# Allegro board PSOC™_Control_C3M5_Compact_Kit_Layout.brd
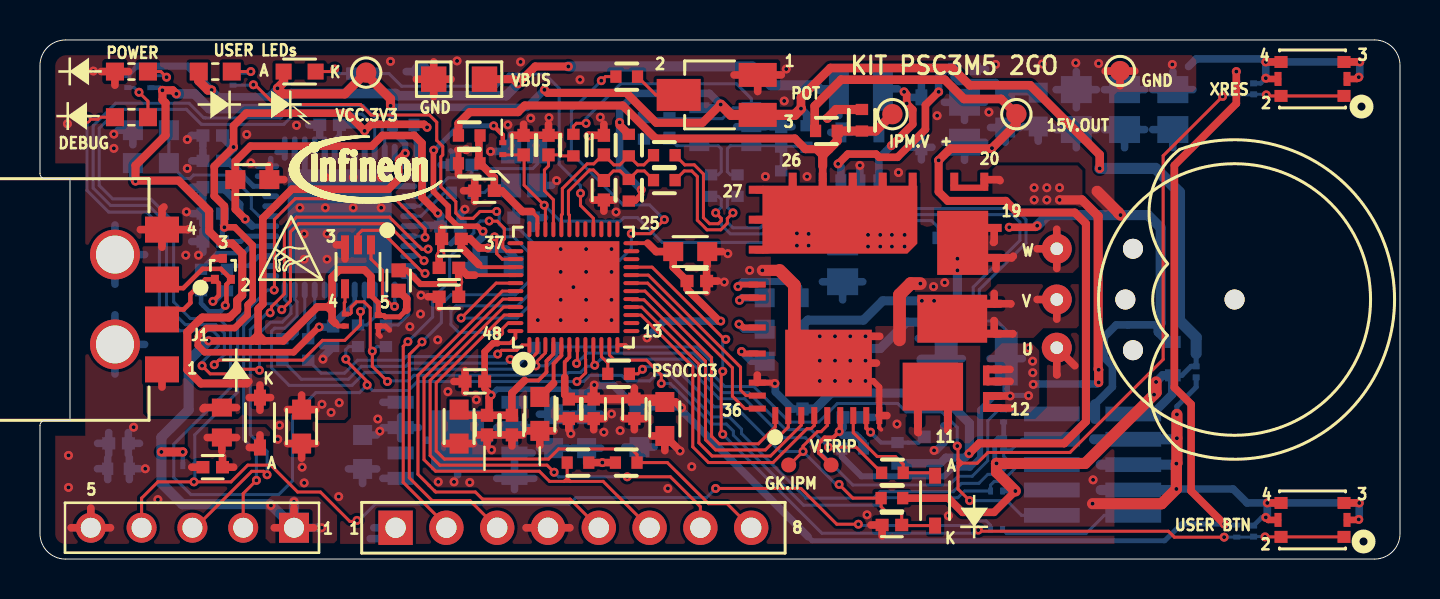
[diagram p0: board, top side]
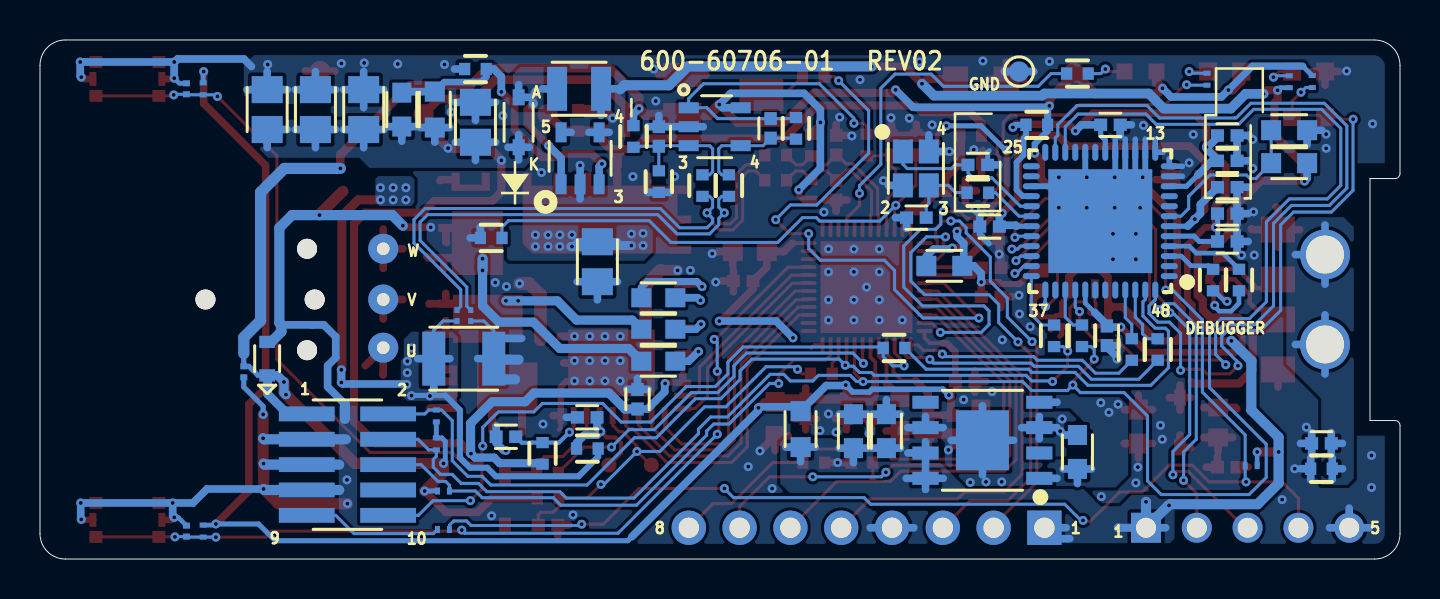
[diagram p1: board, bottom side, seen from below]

Outline 68 x 26 mm; copper layers: TOP, BOTTOM. Coordinates in mm from the lower left corner of the outline.
Outline path: 0,24.73 arc(0.37,25.62) 1.27,26 66.73,26 arc(67.63,25.63) 68,24.73 68,1.27 arc(67.63,0.37) 66.73,0 1.27,0 arc(0.37,0.37) 0,1.27 0,6.69 arc(0.07,6.87) 0.25,6.94 1.5,6.94 1.5,19.05 0.25,19.05 arc(0.07,19.13) 0,19.31 0,24.73

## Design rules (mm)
constraint set DEFAULT: min track width 0.152
net group DP1: nets N11111 N367460
net group DP2: nets IU IU0
net group IDC_LINK_PSEUDO: nets IDC_LINK_PSEUDO_N IDC_LINK_PSEUDO_P

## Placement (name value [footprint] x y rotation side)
C1  2.2nF  [CAPC1608_0603M]  49.91 22.51 90 bottom
C2  10uF  [CAPC2012_0805M]  46.23 21.87 90 bottom
C3  10uF  [CAPC2012_0805M]  51.82 22.51 90 bottom
C4  10uF  [CAPC2012_0805M]  54.23 22.51 90 bottom
C5  10uF  [CAPC2012_0805M]  56.64 22.51 90 bottom
C6  1uF  [CAPC1608_0603M]  16.13 5.36 90 bottom
C7  10uF  [CAPC1608_0603M]  13.08 6.63 270 top
C8  10uF  [CAPC1608_0603M]  25.68 6.41 90 bottom
C9  1uF  [CAPC1608_0603M]  27.33 6.41 90 bottom
C10  2.2uF  [CAPC1005_0402M]  8.64 4.6 180 top
C11  0.1uF  [CAPC1005_0402M]  3.93 5.79 0 bottom
C12  0.1uF  [CAPC1005_0402M]  14.48 21.75 180 bottom
C13  15pF  [CAPC1005_0402M]  21.11 19.74 180 bottom
C14  15pF  [CAPC1005_0402M]  24.18 17.1 0 bottom
C15  4.7uF  [CAPC1608_0603M]  10.62 19 0 top
C16  0.1uF  [CAPC1005_0402M]  8.64 18.62 180 bottom
C17  0.1uF  [CAPC1005_0402M]  20.52 16.65 0 bottom
C18  0.1uF  [CAPC1005_0402M]  14.66 11.18 270 bottom
C19  10uF  [CAPC1005_0402M]  8.64 21.21 180 bottom
C20  0.1uF  [CAPC1005_0402M]  8.64 19.94 180 bottom
C21  0.1uF  [CAPC1005_0402M]  8.64 17.3 180 bottom
C22  0.1uF  [CAPC1005_0402M]  8.64 15.9 180 bottom
C23  0.47nF  [CAPC1005_0402M]  38.13 8.01 90 bottom
C24  22uF  [CAPC2012_0805M]  40.13 14.89 270 bottom
C25  1uF  [CAPC1608_0603M]  37.08 13.09 180 bottom
C26  1uF  [CAPC1608_0603M]  37.08 11.51 0 bottom
C27  1uF  [CAPC1608_0603M]  37.08 9.91 0 bottom
C28  0.47nF  [CAPC1005_0402M]  44.7 6.13 0 bottom
C30  4700pF  [CAPC1005_0402M]  40.64 7.1 0 bottom
C31  10uF  [CAPC1005_0402M]  22.35 6.71 270 top
C32  0.1uF  [CAPC1005_0402M]  23.6 6.71 270 top
C33  10uF  [CAPC1005_0402M]  20.45 13.14 180 top
C34  0.1uF  [CAPC1005_0402M]  20.45 14.58 180 top
C35  10uF  [CAPC1608_0603M]  31.24 7.01 270 top
C36  0.1uF  [CAPC1005_0402M]  29.72 7.52 270 top
C37  10uF  [CAPC1608_0603M]  32.51 15.4 0 top
C38  0.1uF  [CAPC1005_0402M]  32.84 13.92 0 top
C39  10uF  [CAPC1608_0603M]  20.95 6.63 270 top
C40  0.1uF  [CAPC1005_0402M]  21.74 8.89 180 top
C41  1uF  [CAPC1005_0402M]  27.69 7.52 270 top
C42  0.1uF  [CAPC1005_0402M]  26.44 7.52 270 top
C43  4.7uF  [CAPC1608_0603M]  24.99 7.27 270 top
C44  0.22uF  [CAPC1005_0402M]  20.57 16.03 180 top
C45  1UF  [CAPC0603_0201N]  57.81 9.38 90 bottom
C46  100pF  [CAPC1005_0402M]  37.06 21.16 90 bottom
C47  100pF  [CAPC1005_0402M]  25.43 20.73 90 top
C48  0.1uF  [CAPC0603_0201N]  60.68 1.4 270 bottom
C49  0.1uF  [CAPC0603_0201N]  60.68 23.55 270 bottom
C50  100pF  [CAPC1005_0402M]  31.47 21.57 90 bottom
C51  0.1uF  [CAPC1005_0402M]  22.23 18.44 180 top
C52  0.1uF  [CAPC0603_0201N]  16.92 11.94 90 top
C53  10nF  [CAPC1005_0402M]  24.18 20.73 90 top
C56  1nF  [CAPC1005_0402M]  42.6 1.71 180 top
C57  100pF  [CAPC1005_0402M]  28.19 20.73 90 top
C58  100pF  [CAPC1005_0402M]  28.19 18.47 270 top
D1  SCHOTTKY DIODE  [SOD2512X110N]  11 6.84 270 top
D2  SCHOTTKY DIODE  [SOD2512X110N]  44.07 21.87 90 bottom
D3  150060VS75000  [LEDC1608_0603M]  4.57 24.41 90 top
D4  ESD5V3U2U-03F  [SOTFL40P120X59-3N]  9.14 14.53 90 top
D6  ESD5V0D5-TP  [SODFL1608X77M]  56.64 10.04 270 bottom
D7  RED  [LEDC1608X71N_WURTH]  12.98 24.41 180 top
D8  150060VS75000  [LEDC1608_0603M]  8.76 24.41 270 top
D9  150060VS75000  [LEDC1608_0603M]  4.57 22.13 90 top
D10  SCHOTTKY DIODE  [SOD2512X110N]  44.75 2.93 90 top
FB1  60 OHM  [INDC1608_0603N]  9.09 6.84 270 top
FB2  120 OHM  [INDC1005_0402M]  17.93 13.95 90 top
J1  629004113921  [WURTH_629004113921]  6.1 9.5 270 top
J2  HDR 5  [CTST254P1X05_W260]  12.7 1.57 180 top
J3  HDR 5x2  [SAMTEC_FTSH-105-01-L-DV-K-P-TR]  52.63 4.73 270 bottom
J4  CON 8  [RTST254P1X08_W265]  17.78 1.57 0 top
L1  10uH  [IND_74479887310A]  41.05 23.55 0 bottom
M1  BLDC Motor  [MOTOR_1103_KV2230]  59.73 13 0 top
NOREF  -  []  3.75 10.75 90 top
NOREF#2  -  []  35.88 22.25 90 top
NOREF#3  -  []  61.98 0.51 90 top
NOREF#4  -  []  45.11 8.69 90 top
NOREF#5  -  []  44.75 1.68 90 top
NOREF#6  -  []  47.98 12.25 0 top
NOREF#7  -  []  12.17 7.79 90 top
NOREF#8  -  []  0.45 25.69 0 top
NOREF#9  -  []  59.73 7.16 0 top
NOREF#10  -  []  44.79 20.92 90 top
NOREF#11  -  []  32.23 24.95 0 top
NOREF#12  -  []  35.88 22.25 90 top
NOREF#13  -  []  23.56 20.41 0 top
NOREF#14  -  []  17 13.96 90 top
NOREF#15  -  []  61.98 0.51 0 top
NOREF#16  -  []  66.73 0 90 top
NOREF#17  -  []  42.4 22.45 90 top
NOREF#18  -  []  12.18 24.41 0 top
NOREF#19  -  []  54.26 17.04 0 top
NOREF#20  -  []  0 24.73 0 top
NOREF#21  -  []  11 5.59 90 top
NOREF#22  -  []  61.98 22.59 0 top
NOREF#23  -  []  62.05 1.11 90 top
NOREF#24  -  []  23.16 18.26 90 top
NOREF#25  -  []  61.98 22.59 90 top
NOREF#26  -  []  78.49 26.09 0 top
NOREF#27  -  []  18.88 3.45 0 top
NOREF#28  -  []  18.03 5.31 90 top
NOREF#29  -  []  43.34 22.82 0 top
NOREF#30  -  []  22.88 3.45 90 top
NOREF#31  -  []  24.86 18.71 90 top
NOREF#32  -  []  44.03 1.98 90 top
NOREF#33  -  []  59.73 7.16 90 top
NOREF#34  -  []  44.07 20.62 90 top
NOREF#35  -  []  62.05 23.19 90 top
NOREF#36  -  []  23.16 18.26 0 top
NOREF#37  -  []  5.45 19.05 0 top
NOREF#38  -  []  39.7 22.45 0 top
NOREF#39  -  []  45.11 11.39 0 top
NOREF#40  -  []  7.12 -10.33 90 top
NOREF#41  -  []  6.1 9.5 90 top
NOREF#42  -  []  61.9 24.04 0 top
NOREF#43  -  []  62.05 23.19 0 top
NOREF#44  -  []  62.05 1.11 0 top
NOREF#45  -  []  6.1 12 90 top
NOREF#46  -  []  15.9 15.74 0 top
NOREF#47  -  []  45.31 10.04 0 top
NOREF#48  -  []  -337.11 -214.42 0 top
NOREF#49  -  []  18.03 7.85 0 top
NOREF#50  -  []  61.9 1.96 0 top
NOREF#51  -  []  10.27 9.24 0 top
NOREF#52  -  []  14.8 13.96 0 top
NOREF#53  -  []  -37.11 -29.41 0 top
NOREF#54  -  []  44.03 3.88 0 top
NOREF#55  -  []  74.73 66.61 0 top
NOREF#56  -  []  15.25 13.54 90 top
NOREF#57  -  []  39.95 23.55 0 top
NOREF#58  -  []  32.23 21.55 90 top
NOREF#59  -  []  48.21 149.92 0 top
R1  240K  [RESC1608_0603M]  48.26 22.51 90 bottom
R3  1M OHM  [RESC1005_0402M]  3.93 4.52 0 bottom
R4  22K  [RESC1005_0402M]  46.23 24.54 0 bottom
R5  0 OHM  [RESC1005_0402M]  18.16 21.75 0 bottom
R7  560 OHM  [RESC0603_0201N]  5.54 23.91 90 bottom
R8  4.7K  [RESC1608_0603M]  5.54 19.83 180 bottom
R9  0 OHM  [RESC1005_0402M]  12.12 10.49 90 bottom
R10  10K  [RESC1608_0603M]  5.54 21.48 180 bottom
R11  0 OHM  [RESC1005_0402M]  13.41 10.49 90 bottom
R12  510 OHM  [RESC1005_0402M]  21.11 18.34 180 bottom
R13  33 OHM  [RESC1005_0402M]  8.05 13.97 90 bottom
R14  33 OHM  [RESC1005_0402M]  9.35 13.97 90 bottom
R16  1 Ohm  [RESC3225X70N]  46.81 10.04 180 bottom
R18  680K  [RESC1005_0402M]  42.88 5.29 90 bottom
R19  1K  [RESC1005_0402M]  40.63 5.53 0 bottom
R20  10K  [POT_ST-32ETB]  33.93 23.25 90 top
R21  1K  [RESC1005_0402M]  29.34 24.16 0 top
R22  0 Ohm  [RESC1608_0603M]  29.97 6.51 90 bottom
R23  0 Ohm  [RESC1608_0603M]  22.78 14.69 0 bottom
R24  4.7K  [RESC1005_0402M]  26.9 4.83 180 top
R25  4.7K  [RESC1005_0402M]  29.31 4.83 0 top
R26  470 OHM  [RESC1005_0402M]  16.13 24.31 180 bottom
R29  560 OHM  [RESC0603_0201N]  9.65 24.03 90 bottom
R31  1K  [RESC1005_0402M]  34.88 18.7 90 bottom
R32  1K  [RESC1005_0402M]  26.67 20.73 270 top
R33  1K  [RESC1005_0402M]  33.56 18.7 90 bottom
R34  10K  [RESC0603_0201N]  59.84 1.4 270 bottom
R35  4.7K  [RESC0603_0201N]  59.84 23.55 270 bottom
R36  10K  [RESC1005_0402M]  30.2 21.57 90 bottom
R37  47K  [RESC1005_0402M]  21.46 21.21 0 top
R38  9.1K  [RESC1005_0402M]  21.46 19.82 180 top
R39  0 OHM  [RESC1005_0402M]  15.9 11.18 270 bottom
R40  0 OHM  [RESC1005_0402M]  17.3 11.18 270 bottom
R42  10K  [RESC0603_0201N]  47.83 3.41 180 bottom
R43  10K  [RESC0603_0201N]  48.18 5.77 270 bottom
R44  10K  [RESC0603_0201N]  48.18 7.17 90 bottom
R47  560 OHM  [RESC0603_0201N]  4.39 23.91 270 bottom
R48  0 OHM  [RESC1005_0402M]  28.93 9.28 0 top
R50  10K  [RESC0603_0201N]  7.44 4.68 180 bottom
R51  0 OHM  [RESC0603_0201N]  47.83 1.48 0 bottom
R52  4.7K  [RESC0603_0201N]  15.27 11.97 90 top
R53  0 OHM  [RESC1005_0402M]  25.3 10.57 180 bottom
R59  100K  [RESC0603_0201N]  23.14 20.55 270 top
R61  910 OHM  [RESC1005_0402M]  31.22 18.98 180 top
R62  4.7K  [RESC1005_0402M]  42.6 3.05 180 top
R63  4.7K  [RESC1005_0402M]  42.62 4.32 0 top
R64  10K  [RESC1005_0402M]  29.44 18.47 90 top
R66  910 OHM  [RESC1005_0402M]  31.22 20.22 180 top
R67  10K  [RESC1005_0402M]  29.44 20.73 270 top
R68  20K  [RESC1005_0402M]  38.33 21.16 270 bottom
R69  20K  [RESC1005_0402M]  37.06 18.9 270 bottom
R70  0 OHM  [RESC1005_0402M]  39.32 21.44 180 top
R71  0 OHM  [RESC1005_0402M]  41.1 21.98 90 top
SW1  435171014816  [SW_435171014816]  63.63 24.04 180 top
SW2  435171014816  [SW_435171014816]  63.63 1.96 180 top
TH1  100K  [RESC1005_0402M]  45.44 16.08 0 bottom
TIE1  Net Tie  [NET_TIE_COPPERTRACE]  47.15 12.2 90 bottom
TIE2  Net Tie  [NET_TIE_COPPERTRACE]  46.47 12.2 90 bottom
TP2  TP_SMD  [TP102C]  54 24.44 0 top
TP3  TP_SMD  [TP102C]  16.31 24.36 0 top
TP4  TP_SMD  [TP102C]  42.62 22.28 0 top
TP5  TP_SMD  [ICT_TP_SMD_030RD_NSP]  39.56 4.71 0 top
TP8  TP_SMD  [ICT_TP_SMD_030RD_NSP]  37.43 4.71 0 top
TP9  TP_SMD  [TP102C]  19.05 24.41 180 bottom
TP10  TP_SMD  [TP102C]  48.82 22.28 0 top
TP11  PCB SMD TP  [TP_SMD_SQ_127MM]  22.23 24.03 0 top
TP12  PCB SMD TP  [TP_SMD_SQ_127MM]  19.68 24.03 0 top
U1  PSC3M5FDS2LGQ1  [VQFN40P600X600X90-49N_NOFID]  26.67 13.62 90 top
U2  XMC4200-Q48F256 BA  [QFN50P700X700X90-49N_NOFID]  14.99 16.92 0 bottom
U3  IRSM836-044MA  [PQFN65P1200X1200X100-36N_INFINEON]  41.75 13.07 90 top
U4  TLS208D1EJV33XUMA1  [SOIC127P600X170-8_H265X300N]  20.88 5.95 0 bottom
U5  MIC2250-1YD5-TR  [SOT95P280X110-5N]  41 20.07 90 bottom
U6  AD8615AUJZ-REEL  [SOT95P280X110-5N]  34.27 21.65 180 bottom
U7  SN74LVC1G126DCKT  [SOT65P210X110-6N_TI]  15.9 14.64 270 top
Y1  12MHZ  [OSCCC200X250X60-4N_ECS]  24.21 19.56 270 bottom

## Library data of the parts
C1-C28 C30-C53 C56-C58 = CAP-NP
D1 D2 D10 = DIO-SCHOTTKY
D3 D7-D9 = DIO-LED
D4 = ESD5V3U2U-03F
D6 = DIO-TVS
FB1 FB2 = FB
J1 = USB-TYPE_A-2SH
J2 = PLG-5-J
J3 = PLG-10-ODD-EVEN-J
J4 = SKT-8-ALT-J
L1 = IND
M1 = BLDC_Motor_1103-KV2230
R1 R3-R5 R7-R14 R16 R18 R19 R21-R26 R29 R31-R40 R42-R44 R47 R48 R50-R53 R59 R61-R64 R66-R71 = RES
R20 = POT_1_2_3
SW1 SW2 = SWITCH-PB-12-34-G56
TH1 = THERMISTOR
TIE1 TIE2 = NET-TIE2: User Part Number: Part No
TP2-TP4 TP9 TP10 = TP_SMD
TP5 TP8 = TP_SMD: User Part Number: Part No
TP11 TP12 = TP
U1 = IC_PSC3M5FDS2LGQ1_VQFN-48
U2 = IC_XMC4200-Q48F256
U3 = IC_IRSM836-024MA
U4 = IC_TLS208D1EJV33_0
U5 = IC_MIC2250-1YD5
U6 = IC_AD8615AUJZ
U7 = IC_SN74LVC1G126DCK
Y1 = XTAL-4P-2G4G

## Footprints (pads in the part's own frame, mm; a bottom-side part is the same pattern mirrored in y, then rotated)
CAPC0603_0201N
  rect 0.3x0.35 smd: 1(-0.275,0) 2(0.275,0)
CAPC1005_0402M
  rect 0.65x0.62 smd: 1(-0.49,0) 2(0.49,0)
CAPC1608_0603M
  rect 1x0.95 smd: 1(-0.85,0) 2(0.85,0)
CAPC2012_0805M
  rect 1.35x1.55 smd: 1(-1,0) 2(1,0)
CTST254P1X05_W260
  rect 1.5x1.5 hole 1: 1(0,0)
  round 1.5 hole 1: 2(2.54,0) 3(5.08,0) 4(7.62,0) 5(10.16,0)
ICT_TP_SMD_030RD_NSP
  round 0.75 smd: 1(0,0)
IND_74479887310A
  rect 1x2.2 smd: 1(-1.1,0) 2(1.1,0)
INDC1005_0402M
  rect 0.7x0.72 smd: 1(-0.51,0) 2(0.51,0)
INDC1608_0603N
  rect 0.9x1 smd: 1(-0.75,0) 2(0.75,0)
LEDC1608_0603M
  rect 0.9x0.9 smd: A(0,-0.826) K(0,0.826)
LEDC1608X71N_WURTH
  rect 0.8x0.8 smd: A(0.8,0) K(-0.8,0)
MOTOR_1103_KV2230
  round 1 hole 1.4 unplated: (-5.461,0) (-5.08,2.54) (-5.08,-2.54)
  round 0 hole 1.422 unplated: (0,5.84) (0,-5.84) (5.84,0)
  round 1 hole 4 unplated: (0,0)
  round 1.5 hole 0.635: U(-8.89,-2.413) V(-8.89,0) W(-8.89,2.54)
NET_TIE_COPPERTRACE
  rect 0.3x0.25 smd: 1(-0.275,0) 2(0.275,0)
OSCCC200X250X60-4N_ECS
  rect 1.2x1 smd: 1(-0.85,-0.65) 2(0.85,-0.65) 3(0.85,0.65) 4(-0.85,0.65)
POT_ST-32ETB
  rect 1.2x1.9 smd: 1(1,-1.95) 3(-1,-1.95)
  rect 1.6x2.2 smd: 2(0,2)
PQFN65P1200X1200X100-36N_INFINEON
  rect 0.85x0.3 smd: 1(-5.887,4.982) 2(-5.887,4.332) 3(-5.887,3.682) 4(-5.887,3.033) 5(-5.887,2.383) 6(-5.887,1.733) 7(-5.887,1.083) 8(-5.887,0.433) 9(-5.887,-0.217)
  rect 0.78x0.4 smd: 10(-5.923,-2.148) 11(-5.923,-3.648)
  rect 0.4x0.75 smd: 12(-5.507,-5.963) 13(-4.908,-5.963) 14(-4.178,-5.963) 15(-3.578,-5.963) 16(-1.788,-5.963) 17(-0.288,-5.963) 18(2.012,-5.962) 19(3.512,-5.962) 27(5.422,5.932) 28(3.923,5.932) 29(2.422,5.932)
  rect 0.7x0.4 smd: 20(5.928,-5.468) 21(5.928,-3.968)
  rect 0.75x0.4 smd: 22(5.902,-1.887) 23(5.902,-0.388) 24(5.902,1.113) 25(5.902,2.612) 26(5.902,4.113)
  rect 0.3x0.85 smd: 30(0.673,5.882) 31(0.023,5.882) 32(-1.478,5.882) 33(-2.777,5.882) 34(-4.237,5.882) 35(-4.887,5.882) 36(-5.537,5.882)
  rect 3.34x4.33 smd: 39(-3.259,2.322)
QFN50P700X700X90-49N_NOFID
  oval 0.85x0.3 smd: 1(-3.45,2.75) 2(-3.45,2.25) 3(-3.45,1.75) 4(-3.45,1.25) 5(-3.45,0.75) 6(-3.45,0.25) 7(-3.45,-0.25) 8(-3.45,-0.75) 9(-3.45,-1.25) 10(-3.45,-1.75) 11(-3.45,-2.25) 12(-3.45,-2.75) 25(3.45,-2.75) 26(3.45,-2.25) 27(3.45,-1.75) 28(3.45,-1.25) 29(3.45,-0.75) 30(3.45,-0.25) 31(3.45,0.25) 32(3.45,0.75) 33(3.45,1.25) 34(3.45,1.75) 35(3.45,2.25) 36(3.45,2.75)
  oval 0.3x0.85 smd: 13(-2.75,-3.45) 14(-2.25,-3.45) 15(-1.75,-3.45) 16(-1.25,-3.45) 17(-0.75,-3.45) 18(-0.25,-3.45) 19(0.25,-3.45) 20(0.75,-3.45) 21(1.25,-3.45) 22(1.75,-3.45) 23(2.25,-3.45) 24(2.75,-3.45) 37(2.75,3.45) 38(2.25,3.45) 39(1.75,3.45) 40(1.25,3.45) 41(0.75,3.45) 42(0.25,3.45) 43(-0.25,3.45) 44(-0.75,3.45) 45(-1.25,3.45) 46(-1.75,3.45) 47(-2.25,3.45) 48(-2.75,3.45)
  rect 5.2x5.2 smd: H(0,0)
RESC0603_0201N
  rect 0.25x0.35 smd: 1(-0.3,0) 2(0.3,0)
RESC1005_0402M
  rect 0.56x0.62 smd: 1(-0.54,0) 2(0.54,0)
RESC1608_0603M
  rect 1x1 smd: 1(-0.9,0) 2(0.9,0)
RESC3225X70N
  rect 1.15x2.7 smd: 1(-1.5,0) 2(1.5,0)
RTST254P1X08_W265
  rect 1.72x1.72 hole 1.02: 1(0,0)
  round 1.72 hole 1.02: 2(2.54,0) 3(5.08,0) 4(7.62,0) 5(10.16,0) 6(12.7,0) 7(15.24,0) 8(17.78,0)
SAMTEC_FTSH-105-01-L-DV-K-P-TR
  rect 0.74x2.79 smd: 1(-2.54,-2.035) 2(-2.54,2.035) 3(-1.27,-2.035) 4(-1.27,2.035) 5(0,-2.035) 6(0,2.035) 7(1.27,-2.035) 8(1.27,2.035) 9(2.54,-2.035) 10(2.54,2.035)
SOD2512X110N
  rect 0.8x0.6 smd: A(1.25,0) K(-1.25,0)
SODFL1608X77M
  rect 0.61x0.787 smd: A(-0.838,0) K(0.838,0)
SOIC127P600X170-8_H265X300N
  rect 1.31x0.65 smd: 1(-2.845,1.905) 2(-2.845,0.635) 3(-2.845,-0.635) 4(-2.845,-1.905) 5(2.845,-1.905) 6(2.845,-0.635) 7(2.845,0.635) 8(2.845,1.905)
  rect 2.65x3 smd: H(0,0)
SOT65P210X110-6N_TI
  rect 0.95x0.4 smd: 1(-1.1,0.65) 2(-1.1,0) 3(-1.1,-0.65) 4(1.1,-0.65) 5(1.1,0.65)
SOT95P280X110-5N
  rect 1x0.55 smd: 1(-1.3,0.95) 2(-1.3,0) 3(-1.3,-0.95) 4(1.3,-0.95) 5(1.3,0.95)
SOTFL40P120X59-3N
  rect 0.45x0.4 smd: 1(-0.525,0.4) 2(-0.525,-0.4) 3(0.525,0)
SW_435171014816
  rect 0.65x0.6 smd: 1(-1.575,0.85) 2(1.575,0.85) 3(-1.575,-0.85) 4(1.575,-0.85)
  rect 0.35x0.7 smd: 5(-1.725,0) 6(1.725,0)
TP102C
  round 1.016 smd: 1(0,0)
TP_SMD_SQ_127MM
  rect 1.27x1.27 smd: 1(0,0)
VQFN40P600X600X90-49N_NOFID
  oval 0.8x0.2 smd: 1(-2.9,2.2) 2(-2.9,1.8) 3(-2.9,1.4) 4(-2.9,1) 5(-2.9,0.6) 6(-2.9,0.2) 7(-2.9,-0.2) 8(-2.9,-0.6) 9(-2.9,-1) 10(-2.9,-1.4) 11(-2.9,-1.8) 12(-2.9,-2.2) 25(2.9,-2.2) 26(2.9,-1.8) 27(2.9,-1.4) 28(2.9,-1) 29(2.9,-0.6) 30(2.9,-0.2) 31(2.9,0.2) 32(2.9,0.6) 33(2.9,1) 34(2.9,1.4) 35(2.9,1.8) 36(2.9,2.2)
  oval 0.2x0.8 smd: 13(-2.2,-2.9) 14(-1.8,-2.9) 15(-1.4,-2.9) 16(-1,-2.9) 17(-0.6,-2.9) 18(-0.2,-2.9) 19(0.2,-2.9) 20(0.6,-2.9) 21(1,-2.9) 22(1.4,-2.9) 23(1.8,-2.9) 24(2.2,-2.9) 37(2.2,2.9) 38(1.8,2.9) 39(1.4,2.9) 40(1,2.9) 41(0.6,2.9) 42(0.2,2.9) 43(-0.2,2.9) 44(-0.6,2.9) 45(-1,2.9) 46(-1.4,2.9) 47(-1.8,2.9) 48(-2.2,2.9)
  rect 4.6x4.6 smd: H(0,0)
WURTH_629004113921
  rect 1.3x1.7 smd: 1(0,0) 2(-2.5,0) 3(-4.5,0) 4(-7,0)
  round 2.5 hole 1.9: SH1(-1.25,-2.35) SH2(-5.75,-2.35)

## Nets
15V_OUT: C1.1 C2.1 C3.1 C4.1 C5.1 C23.1 D2.K R1.1 R18.1 R70.2 TP10.1(TP) U3.34
GND_EARTH: C11.1 J1.SH1 J1.SH2 R3.1
GND_SIGNAL: C2.2 C3.2 C4.2 C5.2 C6.2 C7.2 C8.2 C9.2 C10.2 C11.2 C12.2 C13.2 C14.2 C15.2 C16.2 C17.2 C18.2 C19.2 C20.2 C21.2 C22.2 C23.2 C24.2 C28.2 C30.2 C31.2 C32.2 C33.2 C34.2 C35.2 C36.2 C37.2 C38.2 C39.2 C40.2 C41.2 C42.2 C43.2 C44.2 C45.1 C46.2 C47.2 C48.1 C49.1 C51.2 C52.1 C53.2 C56.2 C57.2 C58.2 D3.K(CATHODE) D4.3 D6.A J1.4 J2.5 J3.3 J3.5 J3.7 J4.4 R3.2 R4.2 R10.2 R16.2 R20.1 R38.2 R69.2 SW1.3 SW1.4 SW1.5 SW1.6(GND#6) SW2.3 SW2.4 SW2.5 SW2.6(GND#6) TH1.2 TIE2.1 TP2.1(TP) TP9.1(TP) TP12.1(TP) U1.H U2.11 U2.12 U2.13 U2.14 U2.15 U2.16 U2.17 U2.20 U2.27 U2.H U3.9 U3.39 U4.3 U4.6 U4.H U5.2 U6.2(V-) U7.3 Y1.2 Y1.4(GND_2)
VBUS: C6.1 C7.1 D1.K L1.1 R7.1 R8.2 R71.2 TP11.1(TP) U4.1 U4.4 U5.4 U5.5(VIN)
VCC_3V3: C8.1 C9.1 C45.2 C52.2 D6.K(CATHODE) D7.A D8.A FB2.1 J2.1 J3.1 J4.1 R5.1 R20.3 R22.1 R24.1 R25.1 R42.1 R43.1 R44.1 R47.1 R50.2 R52.1 R62.1 R64.1 R67.1 R68.1 TP3.1(TP) U4.7 U4.8 U6.5 U7.5
VCCD: C43.1 U1.5
VDDA: C33.1 C34.1 FB2.2 R23.1 R59.1 U1.41
VDDC: C15.1 C16.1 C17.1 U2.6 U2.31
AN_B2: J4.2 U1.38
AN_B3: J4.3 U1.39
CS: U2.23 U2.40
DEBUG_LED: D9.K(CATHODE) U2.48
EN_IPM: R63.1 U1.7
GK_IPM: C56.1 D10.K R48.2 R62.2 TP8.1(TP) U3.5
IDC_LINK_OPAMP: C47.1 R32.2 U1.33
IDC_LINK_PSEUDO_N: C57.1 R66.2 R67.2 U1.32
IDC_LINK_PSEUDO_P: C58.1 R61.2 R64.2 U1.31
IPM_V+: C24.1 R37.1 R70.1 R71.1 TP4.1(TP) U3.22 U3.23 U3.24 U3.25 U3.26 U3.27 U3.28 U3.29
IU: R31.1 R61.1 TIE1.2(N2)
IU0: R33.1 R66.1 TIE2.2(N2)
M_SPEED_POT: R21.1 U1.42
OBD_PORST_L: J2.4 R50.1 R51.1 U2.32
OBD_TCK: J2.2 U2.34
OBD_TMS: J2.3 U2.33
OBD_UART_RX: R9.2 U2.46
OBD_UART_TX: R11.2 U2.45
OBD_USB_DM: D4.1 J1.2 R14.1
OBD_USB_DP: D4.2(IN2) J1.3 R13.1
OBD_VDDA: C12.1 C18.1 C19.1 C20.1 C21.1 C22.1 R5.2 U2.5 U2.10 U2.18 U2.28 U2.41
P8_0: J4.5 U1.43
P8_1: J4.6 R24.2 U1.44
P8_2: J4.7 U1.45
P8_3: J4.8 R25.2 U1.46
PSC3_UART_RX: R11.1 U1.1
PSC3_UART_TX: R9.1 U1.2
PWMUH: U1.20 U3.35
PWMUL: U1.17 U3.2
PWMVH: U1.19 U3.36
PWMVL: U1.16 U3.3
PWMWH: U1.18 U3.1
PWMWL: U1.15 U3.4
SWD_DIR: U2.37 U7.1
SWD_OUT: U2.35 U7.2
SWDCLK: J3.4 R39.2 R43.2 U1.8 U2.22
SWDIO: J3.2 R40.2 R44.2 R52.2 U1.9 U7.4(Y)
TDO: J3.6 R42.2 U1.11
TEMP: C53.1 R59.2 TH1.1 U1.34
U: M1.U U3.10 U3.11
USER_LED1: R26.1 U1.28
USER_LED2: R29.1 U1.47
USER_SW: C48.2 R34.2 SW2.1 SW2.2 U1.21
V: C26.2 M1.V U3.16 U3.17
V_TRIP: C30.1 R19.2 TP5.1(TP) U3.6
VB1: C25.2 U3.31
VB2: C26.1 U3.32
VB3: C27.1 U3.33
VBACKUP: C31.1 C32.1 C35.1 C36.1 C37.1 C38.1 C39.1 C40.1 C41.1 C42.1 R22.2 R34.1 R35.1 U1.4 U1.6 U1.12 U1.24 U1.48
VDC_LINK: C51.1 R37.2 R38.1 U1.35
VREF_EXT: C44.1 R23.2 U1.40
W: C27.2 M1.W U3.18 U3.19(W/VS3_2)
XRES_L_MCU: C49.2 J3.10 R35.2 R53.1 SW1.1 SW1.2 U1.3(XRES)
XTAL1: C13.1 U2.29 Y1.1
XTAL2: C14.1 R12.1 Y1.3
N07345: FB1.1 J1.1(VBUS)
N07349: C10.1 D1.A FB1.2
N08163: D2.A L1.2 U5.1
N11111: R14.2 U2.3
N20632: C1.2 R1.2 R4.1 U5.3
N32254: R12.2 U2.30
N37178: C28.1 R18.2 U3.8
N38243: C25.1 U3.30
N38502: R16.1 R19.1 TIE1.1 U3.12 U3.13 U3.14 U3.15 U3.20 U3.21
N50220: R8.1 R10.1 U2.7
N86492: D3.A R7.2
N117783: C46.1 R31.2 R68.2 R69.1 U6.3
N117862: C50.1 R33.2 R36.1 U6.4
N117920: C50.2 R32.1 R36.2 U6.1
N133373: D7.K(CATHODE) R26.2
N133421: D8.K(CATHODE) R29.2
N143868: R20.2(WIPER) R21.2
N214953: R39.1 U2.39
N215126: R40.1 U2.36
N223602: J3.9 R51.2
N254765: R53.2 U2.47
N255191: D9.A R47.2
N338896: D10.A R63.2 U3.7
N367460: R13.2 U2.4
N371560: R48.1 U1.10

Pads without a net: J3 8; U1 13 14 22 23 25 26 27 29 30 36 37; U2 1 2 8 9 19 21 24 25 26 38 42 43 44; U4 2 5

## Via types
v1: diameter 0.45, hole 0.2, TOP to BOTTOM, 298 vias

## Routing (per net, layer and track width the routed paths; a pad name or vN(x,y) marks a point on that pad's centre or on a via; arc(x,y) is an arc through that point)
15V_OUT: length 79.2
  TOP w0.305: U3.34 36.75,8.84 v1(36.75,8.79)
  TOP w0.381: U3.34 35.86,9.22
  TOP w0.406: 47.57,20.58 v1(47.6,20.58) ; v1(46.45,5.28) 46.96,5.8 51.21,5.8 52.3,6.89 52.3,16.79 51.74,17.35 48.87,17.35 48.29,17.94 45.39,17.94 44.93,18.39 v1(44.93,19.97)
  TOP w0.432: v1(47.6,20.58) 48.82,21.8 TP10.1 48.06,23.04 46.2,23.04 45.24,24.01 40.06,24.01 38.73,22.69 38.73,21.49 R70.2 ; v1(44.93,19.97) 45.52,20.55 47.55,20.55 47.57,20.58
  BOTTOM w0.381: 54.23,20.6 C4.1 ; C4.1 53.22,21.51 ; C4.1 55.24,21.51 ; C3.1 52.82,21.51 ; C3.1 51.82,20.6 ; C3.1 50.81,21.51 ; D2.K 44.07,21.26 ; D2.K 44.07,19.99 ; D2.K 43.54,20.62 ; D2.K 44.6,20.62 ; 46.23,19.97 C2.1 ; C2.1 45.22,20.87 ; C2.1 47.23,20.87 ; 47.53,21.61 R1.1 ; R1.1 48.26,20.88 ; R1.1 48.99,21.61 ; C23.1 37.62,7.52 36.77,8.37 36.77,8.77 v1(36.75,8.79) ; 56.64,20.6 C5.1 55.64,21.51 ; 49.91,20.93 C1.1 ; C1.1 50.62,21.66 ; C1.1 49.2,21.66
  BOTTOM w0.406: v1(46.45,5.28) 46.25,5.08 45.29,5.08 45.02,4.8 42.92,4.8 R18.1
  BOTTOM w0.457: v1(46.45,5.28) 46.47,5.3 46.47,6.8 45.39,7.88 43.74,7.88 43.3,8.31 39.55,8.31 38.75,7.52 C23.1
GND_EARTH: length 12.1
  BOTTOM w0.381: J1.SH2 3.75,16.73 ; J1.SH2 3.75,13.77 ; J1.SH2 5.23,15.25 ; 2.88,4.52 R3.1 ; R3.1 3.39,5.07 ; R3.1 3.39,3.98 ; 2.88,5.79 C11.1 ; C11.1 3.44,5.25 ; C11.1 3.44,6.34 ; J1.SH1 5.23,10.75 ; J1.SH1 3.75,12.23 ; J1.SH1 3.75,9.27
GND_SIGNAL: length 246.2
  TOP w0.203: U3.9 41.96,6.58 42.06,6.48
  TOP w0.254: 17.02,11.16 16.92,11.26 C52.1 17.27,11.67 17.48,11.46
  TOP w0.305: 20.85,20.5 20.92,20.43 R38.2 ; U3.9 41.96,8.62 41.66,8.92 v1(41.27,8.92)
  TOP w0.33: v1(61.29,24.08) 61.33,24.04 SW1.6 ; SW2.5 65.91,1.96 v1(65.94,1.99) ; v1(65.94,24.13) 65.85,24.04 SW1.5 ; SW2.6 61.42,1.96 v1(61.29,2.09)
  TOP w0.381: J1.4 6.1,17.53 6.2,17.63 ; J1.4 6.1,15.62 ; J1.4 5.02,16.5 ; J1.4 7.4,16.5 7.44,16.54 ; 3.06,24.41 D3.K ; D3.K 4.43,24.41 ; D3.K 3.75,23.73 ; C35.2 30.59,6.17 ; C35.2 31.25,6.17 v1(32,5.41) ; C35.2 31.24,5.43 ; 26.49,1.57 J4.4 24.31,1.57 ; 21.74,17.9 C51.2 ; C51.2 21.74,18.99 ; C51.2 21.18,18.44 ; 41.99,11.16 v1(41.27,11.16) ; 7.59,4.6 C10.2 ; C38.2 33.33,14.47 ; C38.2 33.89,13.92 ; C38.2 33.33,13.38 ; C43.2 25.7,6.42 ; C43.2 24.29,6.42 ; C43.2 24.99,5.69 ; 11.47,19.71 C15.2 12.2,19 ; 24.88,21.22 C47.2 ; C47.2 25.43,21.78 ; C47.2 25.97,21.22 ; TP12.1 19.68,24.9 ; TP12.1 18.82,24.03 ; TP12.1 19.68,23.17 ; TP12.1 20.55,24.03 ; 41.55,1.71 C56.2 42.11,1.16 ; 1.56,1.57 J2.5 ; J2.5 3.52,1.57 ; J2.5 2.54,2.55 ; 12.37,5.78 C7.2 ; C7.2 13.08,5.05 ; C7.2 13.79,5.78 ; 28.19,21.78 C57.2 27.44,21.22 v1(27.41,21.19) ; C40.2 21.25,9.44 ; C40.2 20.7,8.89 ; C40.2 21.25,8.35 ; U3.9 42.35,7.19 ; 21.81,6.22 C31.2 ; C31.2 22.35,5.66 ; C31.2 C32.2 ; C58.2 28.74,17.98 ; C58.2 28.19,17.42 ; C58.2 27.65,17.98 ; 8.71,15.06 D4.3 ; 27.69,6.48 C41.2 ; C41.2 28.23,7.03 ; C41.2 C42.2 ; SW2.3 v1(65.96,2.81) ; 25.9,7.03 C42.2 ; C42.2 26.44,6.48 ; 23.6,5.66 C32.2 ; C32.2 24.14,6.22 ; SW1.3 v1(65.99,24.89) ; U3.39 41.82,9.81 ; 29.18,7.03 C36.2 ; C36.2 29.72,6.48 ; C36.2 30.26,7.03 ; v1(61.37,2.81) SW2.4 ; v1(49.86,16.7) 49.78,16.62 v1(48.46,16.62) ; C34.2 19.96,15.19 v1(20.04,15.27) 20.04,15.87 20.04,15.99 C44.2 20.08,16.57 ; 54,23.7 TP2.1 ; TP2.1 54.74,24.44 ; TP2.1 53.26,24.44 ; 19.96,12.59 C33.2 19.4,13.14 ; 15.25,15.03 U7.3 14.82,15.74 ; 23.64,21.22 C53.2 ; C53.2 24.72,21.22 ; C53.2 24.18,21.78 ; 34.7,24.25 R20.1 ; R20.1 35.88,23.41 ; R20.1 37.07,24.25 ; 33.36,14.69 C37.2 34.09,15.4 ; 20.25,5.78 C39.2 21.66,5.78 ; SW1.4 v1(61.29,24.89) ; 20.92,19.27 R38.2
  TOP w0.559: v1(54.03,17.23) 53.92,17.33 53.92,17.35 52.86,18.42 ; v1(56.85,7.24) v1(56.85,6.05) 56.85,4.81 v1(56.82,4.78) v1(56.82,3.51) 56.08,2.77 v1(52.63,2.77) ; v1(36.12,14.46) 36.98,14.46
  TOP w0.635: 36.98,14.46 37.72,13.72 37.72,11.27 39.17,9.81 U3.39 ; 42.98,10.98 42.98,13.24 43.54,13.8 v1(44.02,13.8)
  BOTTOM w0.152: v1(21.25,17.52) 21.25,17.52 21.14,17.41 ; 45.31,10.78 45.31,11.43 45.8,11.92 TIE2.1
  BOTTOM w0.229: C48.1 61.09,2.09 v1(61.29,2.09) ; C49.1 61.03,23.83 v1(61.29,24.08)
  BOTTOM w0.254: 20.54,20.45 20.62,20.37 C13.2 ; C45.1 57.81,8.62 56.85,7.65 v1(56.85,7.24)
  BOTTOM w0.279: U2.14 12.74,21.03 ; U2.15 13.24,21.03 ; 12.24,21.03 U2.13 11.85,20.37 ; U2.16 13.74,21.03 ; 10.88,19.17 U2.11 ; U2.17 14.24,21.03 ; 11.54,20.05 U2.12 10.88,19.67
  BOTTOM w0.292: v1(14.27,19.12) 14.24,19.15 U2.17 ; v1(17.06,19.12) 17.06,18.96 17.35,18.67 U2.27 ; U2.14 12.74,19.25 v1(12.87,19.12) 12.94,19.12 13.24,19.41 U2.15 ; v1(14.27,17.59) 13.74,18.12 U2.16 ; U2.20 15.74,19.19 v1(15.66,19.12) ; C17.2 21.01,16.27 20.55,15.8
  BOTTOM w0.305: v1(26.54,6.28) 26.54,6.84 26.52,6.86
  BOTTOM w0.381: 45.19,6.67 C28.2 45.19,5.82 44.81,5.44 v1(44.7,5.44) ; 14.11,10.69 C18.2 14.66,10.62 14.15,10.11 v1(14.15,10.01) ; C24.2 41.14,13.89 ; C24.2 40.13,12.98 ; C24.2 39.13,13.89 ; 43.92,11.05 45.03,11.05 45.31,10.78 R16.2 ; v1(21.25,17.52) 21.14,17.41 21.14,17.41 21.01,17.28 C17.2 ; 7.59,18.62 C16.2 8.15,18.08 ; 1.56,1.57 J2.5 ; J2.5 2.54,2.55 ; J2.5 3.52,1.57 ; 45.22,22.87 C2.2 ; C2.2 46.23,21.97 ; C2.2 47.23,22.87 ; 26.62,7.26 C9.2 28.04,7.26 ; v1(61.37,2.81) 60.35,2.81 59.65,3.51 v1(56.82,3.51) ; v1(61.37,2.81) v1(65.96,2.81) 65.96,2.01 v1(65.94,1.99) ; v1(61.37,2.81) 61.37,2.16 v1(61.29,2.09) ; 26.49,1.57 J4.4 24.31,1.57 ; C4.2 54.23,24.42 ; C4.2 55.24,23.51 ; C4.2 53.22,23.51 ; C5.2 56.64,24.42 ; C5.2 57.65,23.51 ; C5.2 55.64,23.51 ; 17.15,6.58 U4.3 ; U4.3 18.03,6.03 ; U4.3 18.03,7.14 ; U4.3 18.92,6.58 ; 8.15,20.49 C20.2 7.59,19.94 ; 19.79,24.41 TP9.1 18.31,24.41 ; C30.2 41.69,7.1 ; R3.2 4.47,5.07 ; R3.2 4.98,4.52 ; R3.2 4.47,3.98 ; v1(7.37,21.01) 7.57,21.21 C19.2 8.15,20.67 ; v1(61.29,24.89) 61.27,24.89 61.12,25.04 57.81,25.04 57.43,24.67 ; v1(61.29,24.89) v1(61.29,24.08) ; v1(61.29,24.89) v1(65.99,24.89) 65.99,24.19 v1(65.94,24.13) ; C6.2 16.84,6.21 ; C11.2 4.42,6.34 ; C11.2 4.42,5.25 ; C11.2 4.97,5.79 ; v1(22.53,20.41) Y1.4 23.56,21.24 ; 51.82,22.6 C3.2 ; C3.2 51.82,24.42 ; C3.2 52.82,23.51 ; C3.2 50.81,23.51 ; C8.2 26.39,7.26 ; C8.2 25.68,7.99 ; C8.2 24.97,7.26 ; 13.99,21.21 C12.2 13.43,21.75 ; C46.2 37.06,22.21 ; C46.2 36.52,21.65 ; C46.2 37.6,21.65 ; 22.84,6.58 U4.6 ; U4.6 23.72,7.14 ; U4.6 24.61,6.58 ; 8.15,16.76 C21.2 ; C21.2 8.15,17.84 ; C21.2 7.59,17.3 ; C22.2 8.15,16.45 ; C22.2 7.59,15.9 ; C22.2 8.15,15.36 ; 52.75,7.76 53.62,8.62 53.62,9.68 53.21,10.09 53.21,11.13 53.81,11.73 54.39,11.73 54.41,11.73 55.93,11.73 55.93,11.73 ; 37.58,8.5 C23.2 ; C23.2 38.67,8.5 ; C23.2 38.13,9.05 ; 4.64,20.75 R10.2 3.91,21.48 ; 20.06,19.74 C13.2 ; 25.23,17.1 C14.2 24.67,16.56 ; 34.84,21.65 U6.2 36.3,21.65 ; 19.32,5.95 U4.H ; U4.H 22.44,5.95 ; U4.H 20.88,7.68 ; U4.H 20.88,4.22 ; R16.2 46.12,10.04 ; R16.2 44.51,10.04 ; R16.2 45.31,9.99 ; 41,19.5 U5.2 41,18.04 ; 46.49,16.08 TH1.2 45.98,16.62 ; 37.6,18.36 R69.2 36.52,18.36 ; Y1.2 25.59,18.71 ; R4.2 47.28,24.54
  BOTTOM w0.508: 53.04,3.46 J3.7 56.77,3.46 v1(56.82,3.51) ; v1(56.85,6.05) 56.79,6 J3.3 52.7,6 ; 53.04,4.73 J3.5 56.77,4.73 v1(56.82,4.78) ; D6.A 56.44,10.88 55.93,11.38 55.93,11.73 56.03,11.83 56.03,16.59 55.4,17.23 v1(54.03,17.23) 50.39,17.23 v1(49.86,16.7) ; 52.75,7.02 52.75,7.76 ; 44.07,9.99 45.31,9.99 45.31,9.5 44.81,9 44.25,9
  vias: v1(1.37,21.8) v1(1.42,5.19) v1(1.42,3.59) v1(2.67,24.44) v1(3.69,21.28) v1(3.69,20.57) v1(4.68,6.6) v1(5.26,4.52) v1(5.89,2.98) v1(7.32,17.39) v1(7.29,15.22) v1(7.37,19.56) v1(7.92,15.22) v1(10.34,21.26) v1(10.54,19.84) v1(11.89,6) v1(11.98,6.7) v1(12.83,21.72) v1(13,17.59) v1(13.11,4.6) v1(13.21,16.29) v1(13.21,15.02) v1(13.21,3.81) v1(14.35,16.29) v1(14.35,15.02) v1(14.94,3.13) v1(15.66,17.59) v1(16.89,7.01) v1(16.99,6.41) v1(17.06,17.59) v1(17.53,24.92) v1(18.49,11.64) v1(19.02,12.27) v1(19.05,13.21) v1(19.89,10.98) v1(19.91,3.87) v1(20.4,8.39) v1(20.7,3.87) v1(20.85,24.95) v1(21.31,20.5) v1(21.49,3.84) v1(21.82,7.98) v1(22.58,5.47) v1(23.39,21.75) v1(24.03,24.9) v1(24.54,22.08) v1(24.89,11.97) v1(25.45,22.1) v1(25.83,18.95) v1(26.04,15.52) v1(26.04,14.38) v1(26.04,12.98) v1(26.04,11.97) v1(26.67,13.62) v1(27,24.01) v1(27.3,15.52) v1(27.3,14.38) v1(27.3,12.98) v1(27.3,11.97) v1(28.02,22.13) v1(28.19,6.35) v1(28.57,15.52) v1(28.57,14.38) v1(28.57,12.98) v1(28.57,11.97) v1(28.57,7.27) v1(28.8,17.38) v1(29.01,6.43) v1(31.39,3.54) v1(32.59,4.63) v1(34.21,13.87) v1(34.39,15.3) v1(35.48,14.46) v1(36.27,19.16) v1(37.21,22.94) v1(37.31,24.54) v1(38.35,19.16) v1(38.99,11.16) v1(38.99,9.94) v1(38.99,8.92) v1(39.75,11.16) v1(39.75,9.94) v1(39.75,8.92) v1(40.51,11.16) v1(40.51,9.94) v1(40.51,8.92) v1(41,19.71) v1(41.27,9.94) v1(41.35,2.21) v1(42.85,6.76) v1(42.93,19.36) v1(44.68,13.64) v1(44.86,22.2) v1(45.24,13.85) v1(45.42,2.17) v1(47.45,22.38) v1(47.78,24.77) v1(50.11,24.79) v1(51.79,24.85) v1(52.65,3.97) v1(52.93,24.82) v1(56.62,24.77)
VBUS: length 75.8
  TOP w0.381: C7.1 13.08,8.22 ; C7.1 13.79,7.48 ; C7.1 12.37,7.48 ; 11,7.46 D1.K ; D1.K 11.53,8.09 ; D1.K 10.47,8.09 ; D1.K 11,8.72 ; 10.45,8.89 10.34,8.79
  TOP w0.406: v1(6.82,23.3) 6.64,23.48 v1(6.12,23.48) 6.12,23 6.28,22.84 6.28,21.22 4.78,19.71 v1(4.78,18.93) 4.8,18.95 6.93,18.95 8.46,17.43 8.46,16.41 9.07,15.8 9.61,15.8 10.11,15.3 10.11,13.21 9.86,12.96 9.86,12.51 9.84,12.49 9.84,12.46 9.5,12.12 9.48,12.12 9.45,12.09 8.12,12.09 8.01,11.99 7.99,11.99 7.37,11.36 7.37,9.48 8.05,8.79 10.34,8.79 ; v1(26.42,24.67) 24.77,24.67 v1(23.9,23.8) 23.67,24.03 TP11.1
  TOP w0.457: v1(39.37,22.08) 39.81,22.52 R71.2
  BOTTOM w0.229: v1(6.12,23.48) 5.99,23.61 R7.1
  BOTTOM w0.381: 17.15,4.04 U4.1 ; R8.2 4.64,19.06 v1(4.78,18.93) ; 39.95,22.22 L1.1 39.21,23.55 ; 41.44,21.37 U5.5 ; 40.55,21.37 U5.4 39.54,21.37 ; 15.42,4.51 C6.1 ; C6.1 16.13,3.78 ; C6.1 16.84,4.51 ; 17.15,7.85 U4.4
  BOTTOM w0.483: v1(6.82,23.3) 7.72,23.3 8.46,22.56 11.81,22.56 12.57,23.31 17.78,23.31 17.89,23.21 23.3,23.21 v1(23.9,23.8)
  BOTTOM w0.508: 38.99,23.52 38.79,23.73 36.55,23.73 35.61,24.67 v1(26.42,24.67)
  vias: v1(14.1,7.75) v1(14.55,7.35) v1(14.96,7.83)
VCC_3V3: length 188.7
  TOP w0.241: R52.1 15.2,11.67 15.2,11.67 14.9,11.67 14.77,11.8
  TOP w0.254: 18.3,12.45 17.97,12.13 17.26,12.13 17.19,12.19 16.94,12.19 C52.2 16.92,12.83 16.55,13.2 U7.5
  TOP w0.305: v1(30.06,18.5) 30.06,18.24 29.76,17.93 R64.1
  TOP w0.381: 14.4,12.63 14.4,12.6 14.61,12.4 ; 14.4,12.63 13.87,12.63 12.17,10.93 11.22,10.93 ; 14.4,12.63 14.61,12.83 ; 10.85,10.93 11.22,10.93 ; 10.85,10.93 10.84,10.92 10.59,10.92 ; 10.85,10.93 10.91,10.99 10.91,11.24 ; 11.22,10.93 10.91,11.24 ; FB2.1 18.34,13.03 18.34,12.49 18.3,12.45 ; 14.77,11.8 14.61,11.97 14.61,12.4 ; 14.61,12.83 14.61,12.4 ; 14.61,12.83 14.61,14.13 14.96,14.48 16.22,14.48 16.55,14.15 U7.5 ; R24.1 v1(28.12,4.83) R25.1 ; R62.1 45.42,3.05 46.13,2.34 47.7,2.34 v1(48.77,3.41) ; 10.91,11.24 10.59,10.92 ; 10.91,11.24 10.91,12.53 10.94,12.56 10.94,12.57 11.14,12.77 11.14,17.07 12.59,18.52 17.42,18.52 17.93,19.03 17.93,19.99 v1(18.26,20.32) ; 10.59,10.92 8.45,10.92 8.44,10.93 v1(8.43,10.93) ; 11.72,1.57 J2.1 ; J2.1 12.7,2.55 ; J2.1 13.68,1.57
  TOP w0.406: R67.1 28.98,21.73 v1(28.98,21.87) ; v1(25.22,23.5) 25.37,23.35 29.31,23.35 30.81,21.85 33.12,21.85 v1(34.04,22.76)
  TOP w0.432: v1(52.98,19.56) 52.98,20.25 49.5,23.73 46.48,23.73 45.62,24.59 39.52,24.59 38.05,23.12 v1(38.05,22.56)
  TOP w0.457: v1(17.53,22.7) 17.53,23.04 16.31,24.26 TP3.1 15.24,23.3 12.15,23.3 v1(11.87,23.58) 12.18,23.88 D7.A ; v1(8.58,23.49) 8.39,23.49 7.94,23.95 D8.A ; v1(7.14,5.36) v1(6.07,5.36)
  TOP w0.508: v1(34.04,22.76) 34.55,22.25 R20.3 37.74,22.25 v1(38.05,22.56)
  TOP w0.559: v1(55.8,8.87) 55.8,8.34 v1(55.7,8.23) 52.26,4.79 47.83,4.79 v1(47.83,4.79) 47.83,4.35 v1(48.77,3.41)
  BOTTOM w0.229: R50.2 v1(7.14,5.36)
  BOTTOM w0.241: 4.86,24.69 R47.1 ; v1(47.83,4.79) 47.83,4.8 47.74,4.89 47.74,5.89 47.91,6.07 48.18,6.07 R43.1 R44.1 ; v1(48.77,3.41) R42.1
  BOTTOM w0.254: D6.K 57.1,9.2 57.55,9.65 C45.2 57.81,10.29
  BOTTOM w0.305: v1(18.26,20.32) 18.26,20.79 17.62,21.43 17.62,21.62
  BOTTOM w0.356: v1(8.58,23.49) 7.38,24.69 4.86,24.69 ; 17.62,21.62 R5.1 17.62,22.64 17.57,22.7
  BOTTOM w0.381: 29.24,5.61 R22.1 ; R22.1 29.97,4.88 ; R22.1 30.7,5.61 ; v1(8.58,23.49) 8.93,23.14 11.44,23.14 v1(11.87,23.58) ; 22.84,4.04 U4.8 ; U4.8 23.72,4.6 ; U4.8 24.69,4.04 ; U4.8 23.72,3.49 ; v1(30.06,18.5) 28.98,19.58 v1(28.98,21.87) 28.98,22.51 29.79,23.32 33.48,23.32 v1(34.04,22.76) 33.87,22.6 U6.5 ; 16.69,1.57 J4.1 17.23,1.02 16.51,1.02 ; v1(17.53,22.7) 17.58,22.7 17.65,22.62 24.35,22.62 v1(25.22,23.5) ; 24.97,5.56 C8.1 26.39,5.56 ; 27.33,4.82 C9.1 ; C9.1 28.04,5.56 ; C9.1 26.62,5.56 ; v1(38.05,22.56) 38.33,22.28 R68.1 ; U4.7 24.61,5.31 ; U4.7 23.72,5.87 ; U4.7 23.72,4.76 ; 11.72,1.57 J2.1
  BOTTOM w0.406: v1(14.08,1.57) J2.1
  BOTTOM w0.432: v1(55.8,8.87) 56.13,9.2 D6.K 56.62,9.17 56.62,8.26 55.63,7.27 J3.1
  BOTTOM w0.457: v1(55.7,8.23) 55.8,8.34 v1(55.8,8.87)
  BOTTOM w0.508: v1(12.7,2.87) J2.1 11.58,2.68 v1(11.55,2.68) 11.48,2.75 7.12,2.75 6.07,3.8 v1(6.07,5.36) 6.07,6.1 7.43,7.46 7.43,9.93 v1(8.43,10.93)
  BOTTOM w0.559: v1(52.98,19.56) 55.78,19.56 56.97,18.37 56.97,11.94 57.81,11.1 57.81,10.29
VCCD: length 3
  TOP w0.191: U1.5 26.07,10.19 26.01,10.13 26.01,10.13 25.77,9.89 25.77,9.88 25.68,9.79 25.68,8.8
  TOP w0.381: 25.68,8.8 C43.1
VDDA: length 21.4
  TOP w0.191: U1.41 21.74,14.22
  TOP w0.229: R59.1 23.14,21.24 v1(22.68,21.7)
  TOP w0.279: v1(19.68,20.48) 19.68,20.43 19.67,20.42 19.67,18.41 20.41,17.67 20.41,17.13 20.88,16.67 21.87,16.67 22.12,16.41 v1(22.15,16.41)
  TOP w0.305: FB2.2 18.34,14.46 19.02,13.77 19.94,13.77 20.04,13.87 v1(20.94,13.87)
  TOP w0.381: 21.74,14.22 21.36,14.22 20.99,14.58 C34.1 v1(20.94,13.87) C33.1
  BOTTOM w0.254: v1(22.68,21.7) 20.95,21.7 19.73,20.48 v1(19.68,20.48)
  BOTTOM w0.381: v1(22.15,16.41) 22.15,16.15 21.82,15.81 21.82,14.75 R23.1 21.32,14.69 20.94,14.3 v1(20.94,13.87)
VDDC: length 22.8
  TOP w0.381: v1(19.89,17.32) 19.1,18.11 19.1,20.83 18.72,21.21 17.12,21.21 16.59,20.68 10.53,20.68 9.77,19.92 C15.1 9.77,17.52 v1(10.26,17.02)
  BOTTOM w0.254: U2.6 10.61,16.67 ; U2.31 19.17,16.67
  BOTTOM w0.381: 10.61,16.67 v1(10.26,17.02) 9.98,17.3 9.98,17.76 9.13,18.62 C16.1 ; v1(19.89,17.32) 20.03,17.18 C17.1 19.97,16.72 19.22,16.72 19.17,16.67
AN_B2: length 20.9
  TOP w0.152: J4.2 20.32,1.68 18.16,3.84 18.16,10.65 v1(18.39,10.89) ; v1(22.46,16.93) 22.47,16.92 22.86,16.92 23.22,16.57 23.22,16.03 23.14,15.96 23.14,15.6 23.32,15.42 U1.38
  BOTTOM w0.152: v1(22.46,16.93) 22.02,16.93 21.7,16.6 21.7,16.34 20.48,15.13 20.48,13.91 19.63,13.06 19.63,12.13 v1(18.39,10.89)
AN_B3: length 25.1
  TOP w0.152: v1(19.1,10.88) 18.47,10.24 18.47,4.07 19.61,2.93 21.5,2.93 J4.3 ; U1.39 23.11,15.02 22.84,15.29 22.84,16.03 v1(22.73,16.14)
  BOTTOM w0.152: v1(22.73,16.14) 23.67,16.14 24.46,15.35 24.46,13.92 23.77,13.24 20.55,13.24 20.07,12.76 20.07,11.84 v1(19.1,10.88)
CS: length 44.2
  TOP w0.152: v1(16.02,12.4) 16.02,11.73 15.24,10.95 14.12,10.95 13.13,9.96 8.94,9.96 v1(8.71,9.73)
  BOTTOM w0.152: v1(8.71,9.73) 9.22,10.24 9.22,11.31 8.79,11.74 7.26,11.74 6.32,12.68 6.32,16.81 5.43,17.71 3.53,17.71 2.66,18.58 2.66,21.7 3.78,22.83 7.45,22.83 8.18,22.1 8.25,22.1 8.26,22.09 12.01,22.09 12.02,22.1 12.04,22.1 12.65,22.71 16.15,22.71 17.11,21.75 17.11,21.22 17.24,21.09 U2.23 ; v1(16.02,12.4) 16.24,12.61 U2.40
DEBUG_LED: length 27.2
  TOP w0.152: v1(10.97,9.45) 10.92,9.5 9.88,9.5 9.65,9.28 8.51,9.28 v1(8.1,9.68) ; v1(2.34,22.03) 2.9,22.03 3,22.13 D9.K
  BOTTOM w0.152: U2.48 12.24,12.99 12.55,12.68 12.55,12.3 12.12,11.87 11.53,11.87 10.97,11.31 v1(10.97,9.45) ; v1(8.1,9.68) 8.1,9.86 8.92,10.67 8.92,11.16 8.64,11.43 6.99,11.43 5.97,12.45 5.97,16.74 5.33,17.38 3.43,17.38 2.35,18.46 2.35,22.02 v1(2.34,22.03)
EN_IPM: length 19.2
  TOP w0.152: v1(39.43,5.61) 40.8,5.61 R63.1 ; v1(26.83,9.8) 26.87,9.84 U1.7
  BOTTOM w0.152: v1(26.83,9.8) 26.84,9.8 27.36,10.32 32.66,10.32 33.3,9.68 33.3,9.15 34.11,8.34 35.43,8.34 37.29,6.48 38.55,6.48 v1(39.43,5.61)
GK_IPM: length 22.7
  TOP w0.152: v1(30.12,9.5) 29.9,9.28 R48.2 ; v1(39.95,3.74) 40.64,3.05 R62.2 42.06,2.62 42.34,2.34 42.96,2.34 43.09,2.22 C56.1 43.12,1.68 D10.K ; U3.5 39.36,6.69 39.06,6.38 38.87,6.38 38.15,5.66 v1(38.15,5.39) 37.47,4.71 TP8.1
  BOTTOM w0.152: v1(30.12,9.5) 30.25,9.63 31.7,9.63 33.71,7.62 34.77,7.62 37.01,5.39 v1(38.15,5.39) 39.8,3.74 v1(39.95,3.74)
IDC_LINK_OPAMP: length 5.3
  TOP w0.152: R32.2 25.98,20.19 25.93,20.24 C47.1 25.43,19.69 25.22,19.49 25.22,18.44 25.67,18 U1.33
IDC_LINK_PSEUDO_N: length 8.1
  TOP w0.152: R66.2 30.19,19.74 29.89,19.74 R67.2 28.99,19.74 28.69,19.74 C57.1 28.14,20.24 27.69,19.79 27.36,19.79 26.12,18.55 26.12,17.27 26.07,17.23 U1.32
IDC_LINK_PSEUDO_P: length 7.6
  TOP w0.152: R61.2 30.22,19.44 29.86,19.44 R64.2 29.01,19.44 28.67,19.44 C58.1 27.67,19.49 27.48,19.49 26.42,18.43 26.42,17.27 26.47,17.23 U1.31
IPM_V+: length 36.6
  TOP w0.381: U3.28 36.41,17 ; U3.24 40.63,18.38 ; 43.63,18.44 U3.22 ; U3.26 37.63,18.38 ; U3.29 36.41,15.5 ; U3.23 42.13,18.38 ; 39.13,19.69 U3.25 39.13,18.38 ; U3.27 36.41,18.5
  TOP w0.406: 39.45,20.53 38.82,20.53 ; 38.82,20.53 38.28,20.53 37.74,21.06 30.78,21.06 29.13,22.71 24.23,22.71 23.9,22.38 21.49,22.38 20.92,21.82 R37.1 ; 38.82,20.53 39.13,20.22
  TOP w0.457: TP4.1 41.78,21.44 R71.1 39.87,21.44 R70.1 39.86,20.94 39.13,20.22 39.13,19.69
  BOTTOM w0.381: 41.14,15.89 C24.1 39.13,15.89
  BOTTOM w0.457: 41.45,15.65 v1(41.4,15.65) 40.37,15.65 C24.1 39.94,15.7 38.48,15.7
  vias: v1(37.85,16.31) v1(37.85,15.7) v1(38.43,16.29) v1(38.43,15.7) v1(41.4,16.24) v1(42.01,16.24) v1(42.01,15.65) v1(42.6,16.24) v1(42.6,15.65) v1(43.23,16.24) v1(43.23,15.65)
IU: length 29.3
  TOP w0.152: v1(34.65,17.34) 34.37,17.06 34.37,16.82 34.04,16.49 33.35,16.49 32.87,16.97 32.87,19.16 32.59,19.44 32.21,19.44 R61.1
  BOTTOM w0.152: R31.1 34.52,18.16 34.37,18.01 34.37,17.62 v1(34.65,17.34) 34.37,17.06 34.37,16.87 34.64,16.59 36.02,16.59 36.98,17.56 48.74,17.56 49.3,17 49.3,15.83 46.96,13.49 46.96,12.66 TIE1.2
IU0: length 28.8
  TOP w0.152: v1(33.78,17.34) 34.06,17.06 34.06,16.95 33.91,16.79 33.48,16.79 33.17,17.1 33.17,19.28 32.72,19.74 32.24,19.74 R66.1
  BOTTOM w0.152: TIE2.2 46.66,12.67 46.66,13.62 49,15.96 49,16.87 48.62,17.25 37.11,17.25 36.14,16.29 34.52,16.29 34.06,16.74 34.06,17.06 v1(33.78,17.34) 34.06,17.62 34.06,18.01 33.91,18.16 R33.1
M_SPEED_POT: length 27.7
  TOP w0.152: v1(21.06,12.07) 22.81,13.82 U1.42 ; v1(31.22,17) 30.52,16.3 v1(29.57,16.3) ; R21.1 28.27,24.16 v1(28.07,23.96)
  BOTTOM w0.152: v1(21.06,12.07) 23.85,12.07 25.27,13.49 25.27,14.46 25.78,14.97 28.98,14.97 29.57,15.55 v1(29.57,16.3) ; v1(31.22,17) 30.48,17.73 29.16,17.73 26.57,20.32 26.57,22.46 v1(28.07,23.96)
OBD_PORST_L: length 72.5
  TOP w0.152: v1(19.25,16.11) 19.25,16.54 17.75,18.05 12.76,18.05 11.72,17.01 11.72,13.49 v1(11.71,13.47) ; J2.4 5.08,3.05 5.89,3.87 v1(7.7,3.87) 9.55,3.87 10.39,4.7 11.54,4.7 12.88,3.36 14.02,3.36 15.49,1.88 15.8,1.88 v1(15.85,1.93) ; v1(40.92,1.74) 39.84,1.74 38.05,3.54 v1(33.78,3.54)
  BOTTOM w0.152: v1(15.85,1.93) 15.95,1.93 16.76,2.75 26.47,2.75 26.8,3.08 33.32,3.08 v1(33.78,3.54) ; v1(19.25,16.11) 19.2,16.11 19.14,16.17 U2.32 ; v1(11.71,13.47) 11.37,13.47 9.88,11.98 9.88,8.36 7.74,6.22 R50.1 7.74,3.91 v1(7.7,3.87) ; v1(40.92,1.74) 40.93,1.74 41,1.68 46.45,1.68 46.68,1.91 47.31,1.91 47.53,1.69 R51.1
OBD_TCK: length 25.7
  TOP w0.152: v1(10.82,3.94) 10.16,3.28 J2.2 ; v1(12.09,12.49) 12.52,12.92 12.52,16.39 12.93,16.79 17.35,16.79 v1(19.2,14.94)
  BOTTOM w0.152: v1(10.82,3.94) 10.82,5.36 10.19,6 10.19,11.68 11.29,12.79 11.79,12.79 v1(12.09,12.49) ; v1(19.2,14.94) 18.97,15.17 U2.34
OBD_TMS: length 27.6
  TOP w0.152: v1(11.35,4.22) 11.18,4.4 10.59,4.4 7.76,1.57 J2.3 ; v1(19.41,15.52) 19.39,15.5 19.09,15.5 17.48,17.12 12.83,17.12 12.22,16.51 12.22,13.28 11.57,12.64 11.57,12.4 v1(11.51,12.33)
  BOTTOM w0.152: U2.33 18.98,15.67 19.13,15.52 v1(19.41,15.52) ; v1(11.51,12.33) 11.43,12.25 11.28,12.25 10.52,11.49 10.52,6.23 11.35,5.39 v1(11.35,4.22)
OBD_UART_RX: length 3.2
  BOTTOM w0.152: U2.46 13.24,12.12 12.87,11.75 12.87,11.28 12.62,11.03 R9.2
OBD_UART_TX: length 2.6
  BOTTOM w0.152: U2.45 13.74,12.09 13.41,11.77 R11.2
OBD_USB_DM: length 6
  TOP w0.229: J1.2 6.6,12.5 7.19,12.5 7.52,12.83 7.52,13.26 8.26,14.01 D4.1 8.94,13.81 8.94,13.2 v1(8.65,12.91)
  BOTTOM w0.229: v1(8.65,12.91) 8.76,12.91 9.29,13.43 R14.1
OBD_USB_DP: length 7.8
  TOP w0.229: J1.3 6.53,13.57 7.16,13.57 8.13,14.53 9.04,14.53 9.54,14.03 D4.2 9.54,13.97 9.32,13.75 9.32,12.76 v1(9.26,12.7)
  BOTTOM w0.229: v1(9.26,12.7) 9.26,12.64 9.03,12.41 8.44,12.41 8.15,12.7 8.15,12.7 8.05,12.81 R13.1
OBD_VDDA: length 51.3
  TOP w0.33: v1(9.22,16.62) 9.74,16.62 10.63,15.72 10.63,12.98 10.4,12.75 10.4,12.74 10.38,12.72 10.38,12.22 9.73,11.57 8.33,11.57 8.23,11.47 8.21,11.47 7.89,11.15 7.89,10.7 8.23,10.36 12.68,10.36 13.94,11.62 v1(13.96,11.62)
  TOP w0.381: v1(19.35,21.62) 19.2,21.77 16.56,21.77 v1(16.23,21.44) 15.34,22.33 10.31,22.33 9.68,21.7 v1(9.68,20.63) 8.71,19.67 8.71,18.18 9.22,17.68 v1(9.22,16.62)
  BOTTOM w0.229: 15.27,12.35 15.74,12.82 U2.41
  BOTTOM w0.254: U2.5 10.3,16.17 10.03,15.9 C22.1 9.12,15.9 9.12,16.51 v1(9.22,16.62) 9.12,16.72 9.12,17.3 C21.1 ; C12.1 14.97,21.22 14.74,20.98 U2.18 ; 10.11,19.23 10.67,18.67 U2.10
  BOTTOM w0.279: 18.7,21.18 18.82,21.06 18.82,20.22 19.18,19.87 19.18,18.49 18.85,18.17 U2.28
  BOTTOM w0.292: v1(19.35,21.62) 19.23,21.75 R5.2 18.7,21.18
  BOTTOM w0.381: v1(13.96,11.62) 14.6,11.62 C18.1 14.66,11.74 15.27,12.35 ; v1(16.23,21.44) 15.93,21.75 C12.1 ; 10.11,19.23 9.4,19.94 C20.1 9.13,20 9.68,20.55 v1(9.68,20.63) 9.68,20.68 9.56,20.68 9.13,21.11 C19.1
P8_0: length 21.7
  TOP w0.152: U1.43 23.12,13.42 18.9,9.2 18.9,4.25 19.46,3.68 19.46,3.68 19.73,3.41 19.73,3.41 19.79,3.36 21.77,3.36 22.12,3 26.51,3 J4.5
P8_1: length 24.2
  TOP w0.152: 26.52,3.89 26.37,4.04 26.36,4.04 ; 26.52,3.89 28.16,3.89 J4.6 ; 26.52,3.89 26.21,3.89 ; 26.21,3.89 25.48,3.89 24.97,4.4 19.78,4.4 19.2,4.98 19.2,9.08 23.15,13.02 U1.44 ; 26.21,3.89 26.36,4.04 ; 26.36,4.04 R24.2
P8_2: length 25.2
  TOP w0.152: U1.45 23.18,12.62 19.51,8.95 19.51,5.19 19.99,4.7 25.35,4.7 v1(25.7,4.35) ; v1(29.36,4.12) 31.52,4.12 33.02,2.62 J4.7
  BOTTOM w0.152: v1(25.7,4.35) 25.93,4.12 v1(29.36,4.12)
P8_3: length 26.8
  TOP w0.152: U1.46 23.21,12.22 19.81,8.82 19.81,5.41 20.22,5.01 25.43,5.01 25.93,5.52 29.57,5.52 29.85,5.23 R25.2 31.37,4.83 33.43,2.77 34.35,2.77 J4.8
PSC3_UART_RX: length 11.9
  TOP w0.152: U1.1 24.1,10.72 23.83,10.45 23.07,10.45 v1(22.89,10.27)
  BOTTOM w0.152: v1(22.89,10.27) 22.76,10.14 18.31,10.14 18.13,9.96 15.88,9.96 15.23,9.31 14.06,9.31 R11.1
PSC3_UART_TX: length 14.1
  TOP w0.152: U1.2 24.87,10.36 24.8,10.29 24.8,10.28 24.61,10.09 23.64,10.09 23.55,10 v1(23.51,10)
  BOTTOM w0.152: v1(23.51,10) 23.32,9.81 18.44,9.81 18.29,9.65 16.07,9.65 15.43,9.01 13.07,9.01 R9.1
PWMUH: length 9.5
  TOP w0.152: U1.20 30.42,14.22 35.03,9.61 35.03,8.46 35.3,8.19 U3.35
PWMUL: length 14.3
  TOP w0.152: U3.2 37.41,6.61 36.27,5.47 33.78,5.47 33.27,5.97 33.27,9.91 30.2,12.98 29.6,12.98 U1.17
PWMVH: length 9.7
  TOP w0.152: U1.19 30.38,13.82 34.62,9.58 34.62,8.16 35.24,7.54 U3.36
PWMVL: length 15
  TOP w0.152: U3.3 38.06,6.7 36.53,5.16 33.6,5.16 32.94,5.82 32.94,9.76 30.08,12.62 U1.16
PWMWH: length 13.6
  TOP w0.152: U1.18 30.25,13.42 33.58,10.09 33.58,6.15 33.96,5.77 35.92,5.77 36.76,6.62 U3.1
PWMWL: length 15.8
  TOP w0.152: U3.4 38.71,6.69 38.56,6.53 38.35,6.53 36.66,4.83 33.42,4.83 32.64,5.62 32.64,9.63 30.05,12.22 U1.15
SWD_DIR: length 4.5
  TOP w0.152: v1(17.73,12.65) 17.65,12.65 17.12,13.19 17.12,14.46 16.55,15.03 U7.1
  BOTTOM w0.152: v1(17.73,12.65) 17.75,12.68 17.75,12.91 17.74,12.93 U2.37
SWD_OUT: length 5.8
  TOP w0.152: U7.2 15.9,16.26 16.1,16.46 17.02,16.46 19.18,14.3 v1(19.25,14.3)
  BOTTOM w0.152: v1(19.25,14.3) 19.18,14.3 18.82,14.66 18.75,14.66 18.74,14.67 U2.35
SWDCLK: length 98.2
  TOP w0.152: v1(16.36,8.72) 16.36,8.89 15.29,9.96 v1(15.29,10.01) ; U1.8 27.27,10 27.28,9.99 27.28,9.32 v1(26.85,8.89)
  BOTTOM w0.152: J3.4 49.1,6 48.57,5.47 R43.2 48.18,5.15 48.34,4.99 48.34,4.6 47.97,4.24 47.39,4.24 46.94,3.79 46.08,3.79 45.66,3.38 42,3.38 41.68,3.05 38.3,3.05 35.08,6.28 35.08,6.51 34.47,7.12 33.63,7.12 31.5,9.25 30.81,9.25 30.48,8.92 29.36,8.92 29.08,9.2 27.48,9.2 27.18,8.9 26.86,8.9 v1(26.85,8.89) 18.87,8.89 18.42,8.44 16.63,8.44 v1(16.36,8.72) 15.98,8.34 13.79,8.34 12.62,7.17 12.62,3.92 11.94,3.23 7.54,3.23 6.69,4.09 6.69,5.75 9.53,8.59 9.53,11.46 8.94,12.04 7.52,12.04 6.68,12.88 6.68,16.89 5.53,18.04 3.63,18.04 2.96,18.71 2.96,21.57 3.91,22.52 7.32,22.52 8.07,21.77 12.19,21.77 12.71,22.29 16.1,22.29 16.74,21.65 U2.22 ; v1(15.29,10.01) 15.29,10.49 15.44,10.64 R39.2
SWDIO: length 48.3
  TOP w0.152: U7.4 15.25,12.87 15.21,12.83 15.21,12.32 R52.2 15.5,12.27 15.56,12.33 15.56,12.62 15.82,12.88 16.21,12.88 16.51,12.58 16.51,10.52 v1(16.62,10.41) 16.62,9.65 v1(17.37,8.89) ; v1(27.74,9.71) 27.74,9.74 27.67,9.81 U1.9
  BOTTOM w0.152: v1(16.62,10.41) 16.85,10.64 R40.2 ; J3.2 48.76,7.27 48.56,7.47 R44.2 47.92,7.47 47.39,6.93 47.39,4.92 46.61,4.14 45.9,4.14 45.46,3.71 40.64,3.71 38.28,6.08 37.19,6.08 35.23,8.03 33.96,8.03 33,8.99 33,9.42 32.41,10.01 28.04,10.01 v1(27.74,9.71) 27.69,9.66 27.34,9.66 27.03,9.35 27.03,9.35 27.02,9.34 26.43,9.34 26.29,9.2 18.7,9.2 18.41,8.92 17.45,8.92 17.42,8.89 v1(17.37,8.89)
TDO: length 27.1
  TOP w0.152: v1(31.06,8.79) 31.06,9.22 30.33,9.96 28.73,9.96 28.47,10.22 U1.11
  BOTTOM w0.152: v1(31.06,8.79) 31.52,8.79 33.55,6.76 34.32,6.76 34.67,6.41 34.67,6.2 38.18,2.7 41.96,2.7 42.33,3.07 45.89,3.07 46.23,3.41 R42.2 47.53,3.7 47.72,3.89 48.11,3.89 48.95,4.73 J3.6
TEMP: length 27
  TOP w0.152: U1.34 25.27,17.64 25.21,17.7 v1(25.21,17.72) 24.21,18.72 24.21,20.22 C53.1 23.15,20.24 R59.2
  BOTTOM w0.152: v1(25.21,17.72) 25.22,17.72 26.02,16.92 29.01,16.92 29.18,17.1 29.87,17.1 31.11,15.85 36.45,15.85 37.54,16.95 44.58,16.95 44.9,16.62 TH1.1
U: length 5.6
  TOP w0.381: 45.39,7.85 U3.11 45.39,6.44 ; 50.85,9.22 50.84,9.24 50.84,10.58 ; 50.84,10.58 51.74,9.68 ; 50.84,10.58 M1.U ; 43.89,7.82 U3.10 43.89,7.04 43.9,7.04 43.9,6.68 43.89,6.67 43.89,6.35 43.92,6.33
USER_LED1: length 17.9
  TOP w0.152: v1(27.03,18.32) 27.03,17.71 27.67,17.06 U1.28
  BOTTOM w0.152: v1(27.03,18.32) 27.03,18.7 25.96,19.77 25.96,23.58 25.25,24.29 23.44,24.29 22.83,23.68 18.08,23.68 17.45,24.31 R26.1
USER_LED2: length 32.4
  TOP w0.152: v1(22.98,11.35) 22.99,11.36 22.99,11.4 23.41,11.82 U1.47 ; v1(22.83,17.41) 22,17.41 21.66,17.06 21.06,17.06 20.79,17.33 20.79,17.9 20.04,18.65 20.04,20.14 20.14,20.24 20.14,20.66 19.84,20.97 19.84,21.87 19.47,22.24 16.55,22.24 16.03,22.76 11.74,22.76 10.75,23.75 v1(10.67,23.75)
  BOTTOM w0.152: v1(22.83,17.41) 22.96,17.28 22.96,16.77 23.21,16.51 23.98,16.51 24.82,15.68 24.82,13.62 23.88,12.68 20.8,12.68 20.55,12.43 20.55,11.74 20.94,11.35 v1(22.98,11.35) ; R29.1 10.65,23.73 v1(10.67,23.75)
USER_SW: length 44.5
  TOP w0.152: v1(46.91,1.45) 46.97,1.39 56.42,1.39 56.72,1.1 v1(59.21,1.1) ; v1(34.14,9.4) 34.06,9.33 34.06,6.33 v1(34.14,6.25) ; SW2.1 SW2.2 v1(61.25,1.11) ; v1(34.29,11) 34.22,11 30.6,14.62 U1.21
  BOTTOM w0.152: v1(46.91,1.45) 46.91,1.44 46.76,1.29 39.1,1.29 v1(34.14,6.25) ; v1(34.14,9.4) 34.14,10.85 v1(34.29,11) ; v1(59.21,1.1) 59.21,1.1 R34.2 60.66,1.1 C48.2 61.24,1.13 v1(61.25,1.11)
V: length 12.9
  TOP w0.381: 48.64,11.28 48.64,11.29 U3.16 47.71,11.93 47.7,11.94 ; 50.84,12.02 M1.V 49.86,13 ; U3.17 48.53,12.79 48.54,12.78 ; U3.17 47.71,13.31 ; U3.17 47.12,12.79
  BOTTOM w0.457: C26.2 38.39,11.97 41.17,11.97 42.14,12.93 v1(44.09,12.93) v1(44.7,12.93)
V_TRIP: length 5.9
  TOP w0.203: v1(39.96,6.39) 39.66,6.09 39.23,6.09 38.95,5.8 38.95,5.32 TP5.1
  TOP w0.254: U3.6 40.01,6.44 v1(39.96,6.39)
  BOTTOM w0.381: R19.2 41.17,5.82 41.03,5.97 40.91,6.08 40.91,6.08 40.79,6.2 40.14,6.2 v1(39.96,6.39) 40.15,6.58 C30.1
VB1: length 2.3
  TOP w0.305: U3.31 35.11,13.1 v1(34.98,12.96)
  BOTTOM w0.381: v1(34.98,12.96) 35.1,13.09 C25.2
VB2: length 2.4
  TOP w0.305: v1(34.95,11.76) 35,11.76 35.17,11.6 U3.32
  BOTTOM w0.381: C26.1 35.2,11.51 v1(34.95,11.76)
VB3: length 2.2
  TOP w0.305: v1(35.08,10.39) 35.17,10.3 U3.33
  BOTTOM w0.381: v1(35.08,10.39) 35.56,9.91 C27.1
VBACKUP: length 102.1
  TOP w0.191: U1.12 29.28,10.72 29.43,10.56 ; U1.4 25.67,10.27 25.43,10.03 25.43,10.02 25.32,9.92 25.32,9.35 24.92,8.95 24.23,8.95 ; 26.24,9.1 26.24,9.87 26.36,9.99 26.36,9.99 26.47,10.11 U1.6 ; 22.87,10.81 22.87,10.81 23.51,10.81 23.77,11.07 U1.48 ; U1.24 30.39,15.82
  TOP w0.33: 22.87,10.81 22.66,10.81 22.23,10.38 C40.1 22.23,8.53 v1(22.56,8.21)
  TOP w0.381: 30.39,15.82 30.81,15.4 C37.1 31.66,14.61 C38.1 32.35,13.52 33.96,11.92 v1(34.04,11.92) ; 24.23,8.95 23.6,8.31 C32.1 C31.1 ; v1(22.56,8.21) 22.45,8.11 22.45,7.3 C31.1 ; 27.69,8.57 C41.1 C42.1 26.44,8.03 26.24,8.23 26.24,9.1 ; 30.54,7.86 C35.1 31.79,7.86 v1(32.08,7.57) ; C31.1 21.24,7.2 C39.1 ; v1(59.21,1.76) 57.56,3.41 57.56,7.75 56.72,8.59 56.72,19.72 59.82,22.81 v1(59.82,24.41) ; C36.1 29.72,8.57
  TOP w0.432: C41.1 C36.1
  TOP w0.457: C36.1 31.09,8.01 C35.1
  BOTTOM w0.229: v1(59.21,1.76) 59.26,1.7 R34.1 ; R35.1 59.84,24.39 v1(59.82,24.41)
  BOTTOM w0.254: 38.4,1.12 38.61,0.92 56.24,0.92 57.07,1.76 v1(59.21,1.76)
  BOTTOM w0.279: v1(27.71,8.72) 27.36,8.36 26.54,8.36 26.4,8.5 22.85,8.5 v1(22.56,8.21)
  BOTTOM w0.381: v1(34.04,11.92) 31.19,11.92 v1(30.35,11.08) ; v1(27.71,8.72) 27.74,8.69 28.69,8.69 R22.2 30.19,7.62 32.03,7.62 v1(32.08,7.57) 32.08,7.45 38.4,1.12
VDC_LINK: length 6.4
  TOP w0.191: U1.35 24.87,17.12 24.59,17.4
  TOP w0.381: 24.59,17.4 24.13,17.4 23.09,18.44 C51.1 22.71,19.1 R38.1 21.95,19.87 21.95,21.16 R37.2
VREF_EXT: length 7
  TOP w0.191: 21.93,14.75 22.06,14.62 U1.40
  TOP w0.381: 21.93,14.75 21.06,15.62 C44.1 21.51,16.03 21.97,15.58 v1(22.38,15.58)
  BOTTOM w0.381: R23.2 23.68,15.16 23.32,15.52 22.53,15.52 22.53,15.53 22.43,15.53 v1(22.38,15.58)
W: length 17.3
  TOP w0.254: U3.19 47.12,16.59
  TOP w0.381: 47.8,14.53 47.8,14.99 U3.18 48.58,15.09 48.67,15.17 ; 50.84,14.56 M1.W ; M1.W 49.86,15.54 ; M1.W 50.84,16.52 ; U3.19 47.71,15.89 47.68,15.85
  BOTTOM w0.457: v1(45.87,14.46) 45.87,12.68 45.06,11.87 43.33,11.87 42.01,10.55 38.57,10.55 C27.2
  BOTTOM w0.508: v1(45.87,14.46) v1(45.87,15.04)
XRES_L_MCU: length 67.6
  TOP w0.152: 45.9,4.81 46.1,4.81 ; 45.9,4.81 45.9,5.01 ; 45.9,4.81 45.9,4.6 ; 46.1,4.81 46.86,4.81 47.4,5.34 51.5,5.34 56.16,10 56.16,20.2 v1(59.13,23.17) ; 46.1,4.81 45.9,5.01 ; 46.1,4.81 45.9,4.6 ; U1.3 25.27,10.33 25.1,10.16 25.1,10.16 24.79,9.85 v1(24.79,9.68) ; v1(45.86,5.66) 45.9,5.62 45.9,5.01 ; v1(46.48,2.93) 45.9,3.51 45.9,4.6 ; SW1.1 SW1.2 61.37,23.19 v1(61.32,23.25)
  BOTTOM w0.152: v1(24.79,9.68) 25.37,9.68 25.84,10.15 R53.1 25.89,10.62 26.49,10.62 32.84,10.62 33.61,9.86 33.61,9.27 34.24,8.64 35.69,8.64 37.47,6.86 38.94,6.86 39.87,7.79 42.89,7.79 43.31,7.37 45.08,7.37 45.86,6.59 v1(45.86,5.66) ; v1(61.32,23.25) 61.29,23.28 C49.2 60.66,23.25 R35.2 59.21,23.25 v1(59.13,23.17) ; J3.10 49.08,2.19 48.34,2.93 v1(46.48,2.93)
